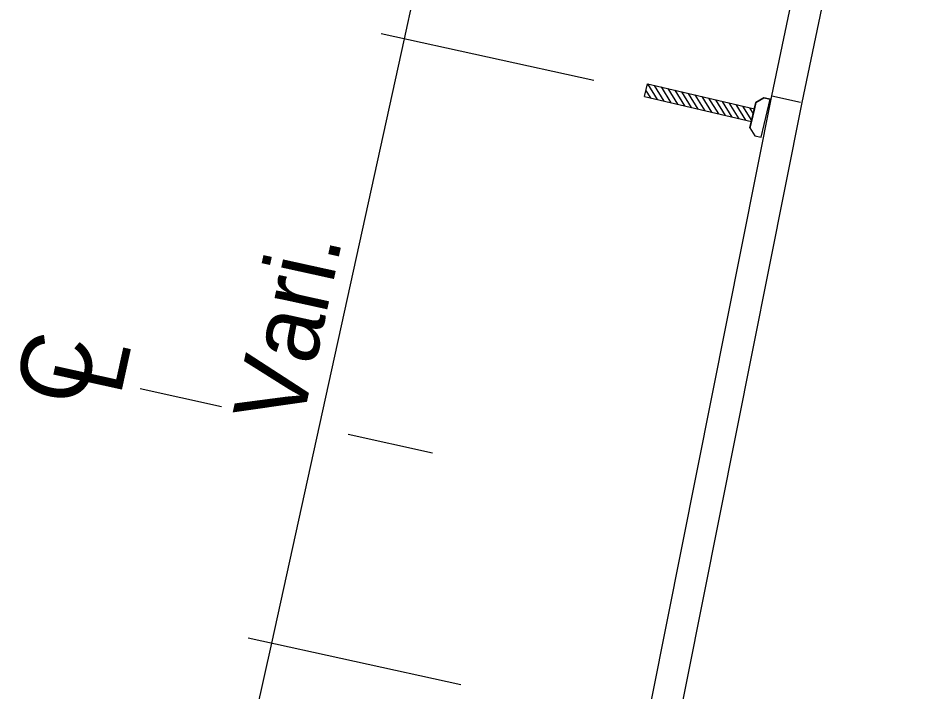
# Model space of a CAD drawing. Extents: x 14104283 to 14121738, y 8635219 to 8671666.
# Drawn here: x 14107411.4 to 14107513.2, y 8639323.3 to 8639400 of the extents above; entities that cross this region are included whole.
import ezdxf

# ---------------------------------------------------------------- set-up
doc = ezdxf.new("R2010")
doc.units = 0
for name, color, linetype in [('Cell', 7, 'Continuous'), ('dsnTextFinalPlan', 7, 'Continuous'), ('TC_SubstrataExistingPavement', 7, 'Continuous'), ('Terrain', 7, 'Continuous')]:
    doc.layers.add(name, color=color, linetype=linetype)

msp = doc.modelspace()

# ---------------------------------------------------------------- linework, layer by layer
at = {"layer": 'Cell'}
for p, q in [((14107482.68, 8639391.08), (14107483.02, 8639392.52)), ((14107483.02, 8639392.52), (14107495.21, 8639389.66)), ((14107484.18, 8639390.73), (14107483.07, 8639392.51)), ((14107484.95, 8639390.54), (14107483.85, 8639392.33)), ((14107485.72, 8639390.36), (14107484.62, 8639392.15)), ((14107486.5, 8639390.18), (14107485.39, 8639391.97)), ((14107482.68, 8639391.08), (14107494.87, 8639388.21)), ((14107483.41, 8639390.91), (14107482.85, 8639391.8)), ((14107487.27, 8639390), (14107486.17, 8639391.78)), ((14107488.04, 8639389.82), (14107486.94, 8639391.6)), ((14107488.82, 8639389.64), (14107487.71, 8639391.42)), ((14107489.59, 8639389.45), (14107488.48, 8639391.24)), ((14107490.36, 8639389.27), (14107489.26, 8639391.06)), ((14107491.14, 8639389.09), (14107490.03, 8639390.88)), ((14107496.27, 8639390.93), (14107495.38, 8639390.38)), ((14107495.38, 8639390.38), (14107496.27, 8639390.93)), ((14107496.99, 8639390.77), (14107496.27, 8639390.93)), ((14107496.27, 8639390.93), (14107496.99, 8639390.77)), ((14107491.91, 8639388.91), (14107490.8, 8639390.69)), ((14107492.68, 8639388.73), (14107491.58, 8639390.51)), ((14107493.46, 8639388.54), (14107492.35, 8639390.33)), ((14107494.23, 8639388.36), (14107493.12, 8639390.15)), ((14107494.9, 8639388.34), (14107493.9, 8639389.97)), ((14107494.7, 8639387.49), (14107495.38, 8639390.38)), ((14107495.38, 8639390.38), (14107495.21, 8639389.66)), ((14107495.97, 8639386.43), (14107496.99, 8639390.77)), ((14107495.97, 8639386.43), (14107496.99, 8639390.77)), ((14107495.09, 8639389.11), (14107494.67, 8639389.79)), ((14107495.21, 8639389.66), (14107494.87, 8639388.21)), ((14107494.87, 8639388.21), (14107494.7, 8639387.49)), ((14107494.7, 8639387.49), (14107495.25, 8639386.6)), ((14107494.7, 8639387.49), (14107495.25, 8639386.6)), ((14107495.25, 8639386.6), (14107495.97, 8639386.43)), ((14107495.25, 8639386.6), (14107495.97, 8639386.43))]:
    msp.add_line(p, q, dxfattribs=at)
at = {"layer": 'dsnTextFinalPlan'}
for p, q in [((14107455.37, 8639397.63), (14107463.96, 8639436.7)), ((14107476.92, 8639392.89), (14107452.7, 8639398.22)), ((14107440.25, 8639328.81), (14107455.37, 8639397.63)), ((14107425.26, 8639357.8), (14107434.55, 8639355.76)), ((14107448.95, 8639352.6), (14107458.56, 8639350.49)), ((14107429.95, 8639281.93), (14107440.25, 8639328.81)), ((14107461.8, 8639324.07), (14107437.58, 8639329.39))]:
    msp.add_line(p, q, dxfattribs=at)
at = {"layer": 'TC_SubstrataExistingPavement'}
msp.add_line((14107497.18, 8639391.15), (14107500.47, 8639390.42), dxfattribs=at)
msp.add_lwpolyline([(14107513.16, 8639450.46), (14107500.59, 8639390.4), (14107481.87, 8639296.22), (14107478.45, 8639296.97)], dxfattribs=at)
at = {"layer": 'Terrain'}
msp.add_lwpolyline([(14107471.43, 8639257.56), (14107478.45, 8639296.97), (14107497.18, 8639391.15), (14107509.74, 8639451.21)], dxfattribs=at)

# ---------------------------------------------------------------- texts
at = {"layer": 'dsnTextFinalPlan'}
for s, p in [('Vari.', (14107443.61, 8639353.32)), ('C', (14107418.76, 8639355.52)), ('L', (14107423.01, 8639356.83))]:
    msp.add_text(s, height=8, rotation=77.6078, dxfattribs=at).set_placement(p)

doc.saveas('drawing.dxf')
